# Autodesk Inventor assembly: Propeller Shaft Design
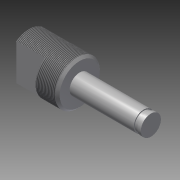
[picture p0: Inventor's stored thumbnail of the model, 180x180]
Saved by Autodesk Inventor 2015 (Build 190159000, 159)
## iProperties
Created: 2007-02
Part Number: Propeller Shaft Design
Document SubType Name: Assembly
Designer: Autodesk, Inc.
Mass: 114.771 g
Surface Area: 43.4472 cm^2
Volume: 14.6205 cm^3
Density: 7.85 g/cm^3
ClientObjectVersion: 1
Author: Autodesk, Inc.
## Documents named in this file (2)
- C:\Users\Public\Documents\Autodesk\Inventor 2015\Samples\Models\Assemblies\Blower\Blower\Design Accelerator\Propeller Shaft Design1.iam
- C:\Users\Public\Documents\Autodesk\Inventor 2015\Samples\Models\Assemblies\Blower\Blower\Design Accelerator\Fan Shaft1.ipt
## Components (1 placed, 1 different names)
1. SH - 0001 :1
